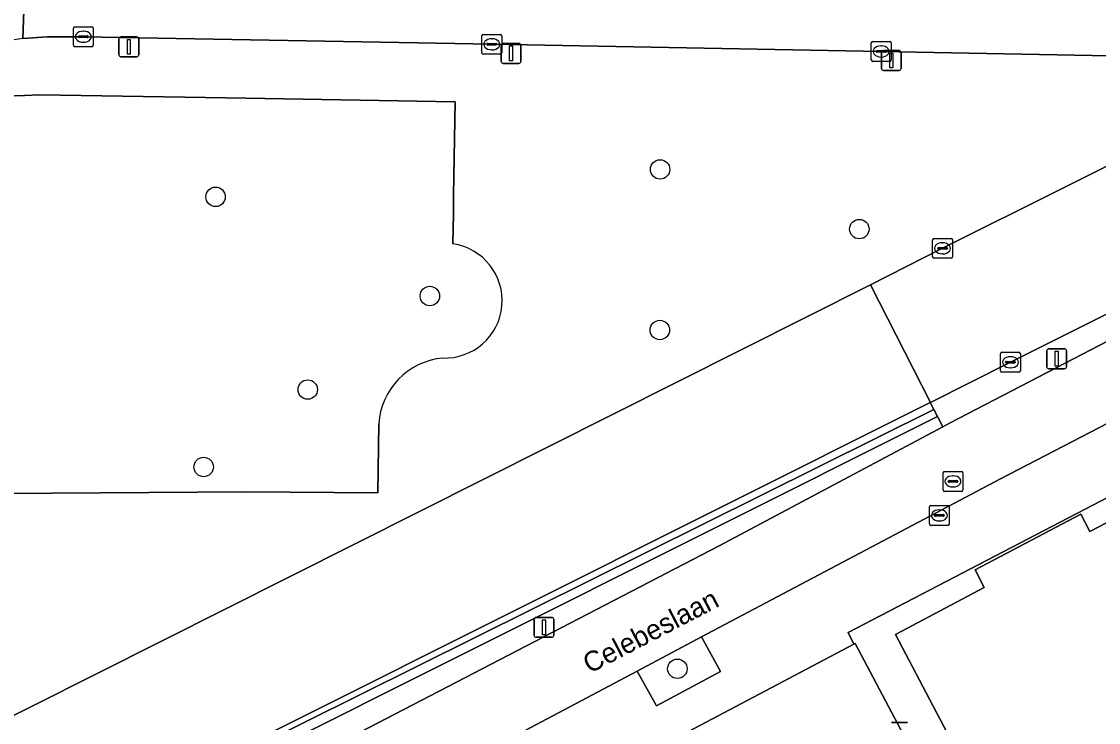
# Model space of a CAD drawing. Extents: x 162879 to 165540, y 384011 to 385181.
# Drawn here: x 162988.7 to 163042.9, y 384224.4 to 384259.7 of the extents above; entities that cross this region are included whole.
import ezdxf

# ---------------------------------------------------------------- set-up
doc = ezdxf.new("R2010")
doc.units = 0
for name, color, linetype in [('IMGEO_Berm_groen', 7, 'Continuous'), ('IMGEO_Berm_open', 7, 'Continuous'), ('IMGEO_Boom', 7, 'Continuous'), ('IMGEO_Fietspad_gesloten', 7, 'Continuous'), ('IMGEO_Groenvoorziening', 7, 'Continuous'), ('IMGEO_Kolk', 7, 'Continuous'), ('IMGEO_Lichtmast', 7, 'Continuous'), ('IMGEO_Muur', 7, 'Continuous'), ('IMGEO_Openbare_ruimte_label', 7, 'Continuous'), ('IMGEO_Parkeervlak_open', 7, 'Continuous'), ('IMGEO_Rijbaan_lokaal_gesloten', 7, 'Continuous'), ('IMGEO_Rijbaan_lokaal_open', 7, 'Continuous'), ('IMGEO_Rijbaan_regionaal_gesloten', 7, 'Continuous'), ('IMGEO_Rioolput', 7, 'Continuous'), ('IMGEO_Verkeerseiland_open', 7, 'Continuous'), ('IMGEO_Voetpad_onverhard', 7, 'Continuous'), ('IMGEO_Voetpad_open', 7, 'Continuous')]:
    doc.layers.add(name, color=color, linetype=linetype)

msp = doc.modelspace()

# ---------------------------------------------------------------- linework, layer by layer
at = {"layer": 'IMGEO_Berm_groen'}
for points in [[(163048.953, 384257.731), (163045.81, 384257.88), (163043.434, 384257.933), (163031.941, 384258.147), (163012.363, 384258.506), (162991.826, 384258.886), (162990.027, 384258.876), (162988.781, 384258.793)], [(163010.404, 384248.476), (163010.429, 384250), (163010.444, 384250.927), (163010.506, 384254.69), (163010.521, 384255.618), (163000, 384255.799), (162996.931, 384255.852), (162989.625, 384255.961), (162988.873, 384255.939), (162983.391, 384255.751)], [(162983.391, 384255.751), (162988.873, 384255.939), (162989.625, 384255.961), (162996.931, 384255.852), (163000, 384255.799), (163010.521, 384255.618), (163010.506, 384254.69), (163010.444, 384250.927), (163010.429, 384250), (163010.404, 384248.476)], [(162985.976, 384223.591), (163031.406, 384246.417), (163035.025, 384248.253), (163047.128, 384254.295)], [(162972.327, 384237.887), (162974.021, 384236.951), (162975.613, 384235.849), (163000, 384236.01), (163006.636, 384235.968), (163006.675, 384239.422)], [(163006.675, 384239.422), (163006.636, 384235.968), (163000, 384236.01), (162975.613, 384235.849)]]:
    msp.add_lwpolyline(points, dxfattribs=at)
for centre, radius, start, end in [((162995.742, 384213.765), 45.562, 98.788, 116.0822), ((163009.999, 384245.62), 2.884, 267.7669, 81.9361), ((163009.999, 384245.62), 2.884, 267.7669, 81.9361), ((163010.234, 384239.188), 3.567, 95.5899, 176.2356), ((163010.234, 384239.188), 3.567, 95.5899, 176.2356)]:
    msp.add_arc(centre, radius, start, end, dxfattribs=at)
at = {"layer": 'IMGEO_Berm_open'}
for points in [[(162947.574, 384196.509), (162949.271, 384197.384), (163000, 384222.957), (163034.579, 384240.157)], [(163034.579, 384240.157), (163034.397, 384240.497), (162949.477, 384198.002)]]:
    msp.add_lwpolyline(points, dxfattribs=at)
at = {"layer": 'IMGEO_Boom'}
for centre in [(163020.825, 384252.217), (162998.475, 384250.839), (163030.841, 384249.219), (163009.249, 384245.853), (163020.811, 384244.148), (163003.109, 384241.152), (162997.875, 384237.259), (163021.693, 384227.118)]:
    msp.add_circle(centre, 0.489, dxfattribs=at)
at = {"layer": 'IMGEO_Fietspad_gesloten'}
for points in [[(163034.397, 384240.497), (163034.42, 384240.509), (163031.406, 384246.417), (162985.976, 384223.591), (162975.103, 384218.147), (162946.359, 384203.806)], [(162949.477, 384198.002), (163034.397, 384240.497)]]:
    msp.add_lwpolyline(points, dxfattribs=at)
at = {"layer": 'IMGEO_Groenvoorziening'}
msp.add_lwpolyline([(163046.764, 384236.284), (163046.789, 384236.297), (163046.732, 384236.407), (163046.287, 384237.263), (163030.287, 384228.938), (163030.573, 384228.36), (163030.638, 384228.394), (163040.222, 384210.272), (163041.946, 384211.188), (163032.652, 384228.845), (163037.115, 384231.211), (163036.667, 384232.088), (163041.974, 384234.886), (163042.428, 384234.014)], close=True, dxfattribs=at)
at = {"layer": 'IMGEO_Kolk'}
for p, q in [((162991.325, 384258.46), (162991.325, 384259.312)), ((162991.4, 384259.386), (162992.252, 384259.386)), ((162991.813, 384259.166), (162991.838, 384259.166)), ((162992.326, 384259.312), (162992.326, 384258.46)), ((162991.584, 384258.88), (162991.584, 384258.892)), ((162992.022, 384258.843), (162991.624, 384258.843)), ((162991.627, 384258.929), (162992.025, 384258.929)), ((162991.836, 384258.606), (162991.811, 384258.606)), ((162992.068, 384258.892), (162992.068, 384258.88)), ((163011.862, 384258.08), (163011.862, 384258.932)), ((163011.937, 384259.006), (163012.789, 384259.006)), ((163012.121, 384258.5), (163012.121, 384258.512)), ((163012.164, 384258.549), (163012.562, 384258.549)), ((163012.35, 384258.786), (163012.375, 384258.786)), ((163012.605, 384258.512), (163012.605, 384258.5)), ((163012.863, 384258.932), (163012.863, 384258.08)), ((163031.44, 384257.721), (163031.44, 384258.573)), ((163031.515, 384258.647), (163032.367, 384258.647)), ((163032.441, 384258.573), (163032.441, 384257.721)), ((162992.252, 384258.386), (162991.4, 384258.386)), ((163012.789, 384258.006), (163011.937, 384258.006)), ((163012.559, 384258.463), (163012.161, 384258.463)), ((163012.373, 384258.226), (163012.348, 384258.226)), ((163031.699, 384258.141), (163031.699, 384258.153)), ((163032.137, 384258.104), (163031.739, 384258.104)), ((163031.742, 384258.19), (163032.14, 384258.19)), ((163031.928, 384258.427), (163031.953, 384258.427)), ((163032.183, 384258.153), (163032.183, 384258.141)), ((163032.367, 384257.647), (163031.515, 384257.647)), ((163031.951, 384257.867), (163031.926, 384257.867)), ((163034.524, 384247.827), (163034.524, 384248.679)), ((163034.599, 384248.753), (163035.451, 384248.753)), ((163034.783, 384248.247), (163034.783, 384248.259)), ((163034.826, 384248.296), (163035.224, 384248.296)), ((163035.012, 384248.533), (163035.037, 384248.533)), ((163035.267, 384248.259), (163035.267, 384248.247)), ((163035.525, 384248.679), (163035.525, 384247.827)), ((163035.451, 384247.753), (163034.599, 384247.753)), ((163035.221, 384248.21), (163034.823, 384248.21)), ((163035.035, 384247.973), (163035.01, 384247.973)), ((163037.939, 384242.1), (163037.939, 384242.952)), ((163038.014, 384243.026), (163038.866, 384243.026)), ((163038.427, 384242.806), (163038.452, 384242.806)), ((163038.94, 384242.952), (163038.94, 384242.1)), ((163038.198, 384242.52), (163038.198, 384242.532)), ((163038.636, 384242.483), (163038.238, 384242.483)), ((163038.241, 384242.569), (163038.639, 384242.569)), ((163038.682, 384242.532), (163038.682, 384242.52)), ((163038.866, 384242.026), (163038.014, 384242.026)), ((163038.45, 384242.246), (163038.425, 384242.246)), ((163034.365, 384234.401), (163034.365, 384235.253)), ((163034.44, 384235.327), (163035.292, 384235.327)), ((163035.366, 384235.253), (163035.366, 384234.401)), ((163034.624, 384234.821), (163034.624, 384234.833)), ((163035.062, 384234.784), (163034.664, 384234.784)), ((163034.667, 384234.87), (163035.065, 384234.87)), ((163034.853, 384235.107), (163034.878, 384235.107)), ((163035.108, 384234.833), (163035.108, 384234.821)), ((163035.292, 384234.327), (163034.44, 384234.327)), ((163034.876, 384234.547), (163034.851, 384234.547))]:
    msp.add_line(p, q, dxfattribs=at)
for points in [[(162991.325, 384258.46), (162991.325, 384259.312)], [(162991.4, 384259.386), (162992.252, 384259.386)], [(162992.326, 384259.312), (162992.326, 384258.46)], [(163011.862, 384258.08), (163011.862, 384258.932)], [(163011.937, 384259.006), (163012.789, 384259.006)], [(163012.863, 384258.932), (163012.863, 384258.08)], [(163031.44, 384257.721), (163031.44, 384258.573)], [(163031.515, 384258.647), (163032.367, 384258.647)], [(163032.441, 384258.573), (163032.441, 384257.721)], [(162992.252, 384258.386), (162991.4, 384258.386)], [(163012.789, 384258.006), (163011.937, 384258.006)], [(163032.367, 384257.647), (163031.515, 384257.647)], [(163034.524, 384247.827), (163034.524, 384248.679)], [(163034.599, 384248.753), (163035.451, 384248.753)], [(163035.525, 384248.679), (163035.525, 384247.827)], [(163035.451, 384247.753), (163034.599, 384247.753)], [(163037.939, 384242.1), (163037.939, 384242.952)], [(163038.014, 384243.026), (163038.866, 384243.026)], [(163038.94, 384242.952), (163038.94, 384242.1)], [(163038.866, 384242.026), (163038.014, 384242.026)], [(163034.365, 384234.401), (163034.365, 384235.253)], [(163034.44, 384235.327), (163035.292, 384235.327)], [(163035.366, 384235.253), (163035.366, 384234.401)], [(163035.292, 384234.327), (163034.44, 384234.327)]]:
    msp.add_lwpolyline(points, dxfattribs=at)
for centre, radius, start, end in [((162991.402, 384259.31), 0.0765, 91.552, 178.448), ((162991.402, 384259.31), 0.0765, 91.552, 178.448), ((162992.25, 384259.31), 0.0765, 1.552, 88.448), ((162992.25, 384259.31), 0.0765, 1.552, 88.448), ((162991.624, 384258.889), 0.0403, 85.8775, 175.7526), ((162991.621, 384258.879), 0.0366, 178.938, 274.7102), ((162992.025, 384258.886), 0.043, 264.8664, 352.4533), ((162992.029, 384258.891), 0.0386, 1.7309, 96.639), ((163011.939, 384258.93), 0.0765, 91.552, 178.448), ((163011.939, 384258.93), 0.0765, 91.552, 178.448), ((163012.161, 384258.509), 0.0403, 85.8775, 175.7526), ((163012.566, 384258.511), 0.0386, 1.7309, 96.639), ((163012.787, 384258.93), 0.0765, 1.552, 88.448), ((163012.787, 384258.93), 0.0765, 1.552, 88.448), ((163031.517, 384258.571), 0.0765, 91.552, 178.448), ((163031.517, 384258.571), 0.0765, 91.552, 178.448), ((163032.365, 384258.571), 0.0765, 1.552, 88.448), ((163032.365, 384258.571), 0.0765, 1.552, 88.448), ((162991.402, 384258.462), 0.0765, 181.552, 268.448), ((162991.402, 384258.462), 0.0765, 181.552, 268.448), ((162992.25, 384258.462), 0.0765, 271.552, 358.448), ((162992.25, 384258.462), 0.0765, 271.552, 358.448), ((163011.939, 384258.082), 0.0765, 181.552, 268.448), ((163011.939, 384258.082), 0.0765, 181.552, 268.448), ((163012.158, 384258.499), 0.0366, 178.938, 274.7102), ((163012.562, 384258.506), 0.043, 264.8664, 352.4533), ((163012.787, 384258.082), 0.0765, 271.552, 358.448), ((163012.787, 384258.082), 0.0765, 271.552, 358.448), ((163031.739, 384258.15), 0.0403, 85.8775, 175.7526), ((163031.736, 384258.14), 0.0366, 178.938, 274.7102), ((163032.14, 384258.147), 0.043, 264.8664, 352.4533), ((163032.144, 384258.152), 0.0386, 1.7309, 96.639), ((163031.517, 384257.723), 0.0765, 181.552, 268.448), ((163031.517, 384257.723), 0.0765, 181.552, 268.448), ((163032.365, 384257.723), 0.0765, 271.552, 358.448), ((163032.365, 384257.723), 0.0765, 271.552, 358.448), ((163034.601, 384248.677), 0.0765, 91.552, 178.448), ((163034.601, 384248.677), 0.0765, 91.552, 178.448), ((163034.823, 384248.256), 0.0403, 85.8775, 175.7526), ((163034.82, 384248.246), 0.0366, 178.938, 274.7102), ((163035.224, 384248.253), 0.043, 264.8664, 352.4533), ((163035.228, 384248.258), 0.0386, 1.7309, 96.639), ((163035.449, 384248.677), 0.0765, 1.552, 88.448), ((163035.449, 384248.677), 0.0765, 1.552, 88.448), ((163034.601, 384247.829), 0.0765, 181.552, 268.448), ((163034.601, 384247.829), 0.0765, 181.552, 268.448), ((163035.449, 384247.829), 0.0765, 271.552, 358.448), ((163035.449, 384247.829), 0.0765, 271.552, 358.448), ((163038.016, 384242.95), 0.0765, 91.552, 178.448), ((163038.016, 384242.95), 0.0765, 91.552, 178.448), ((163038.864, 384242.95), 0.0765, 1.552, 88.448), ((163038.864, 384242.95), 0.0765, 1.552, 88.448), ((163038.238, 384242.529), 0.0403, 85.8775, 175.7526), ((163038.235, 384242.519), 0.0366, 178.938, 274.7102), ((163038.639, 384242.526), 0.043, 264.8664, 352.4533), ((163038.643, 384242.531), 0.0386, 1.7309, 96.639), ((163038.016, 384242.102), 0.0765, 181.552, 268.448), ((163038.016, 384242.102), 0.0765, 181.552, 268.448), ((163038.864, 384242.102), 0.0765, 271.552, 358.448), ((163038.864, 384242.102), 0.0765, 271.552, 358.448), ((163034.442, 384235.251), 0.0765, 91.552, 178.448), ((163034.442, 384235.251), 0.0765, 91.552, 178.448), ((163035.29, 384235.251), 0.0765, 1.552, 88.448), ((163035.29, 384235.251), 0.0765, 1.552, 88.448), ((163034.664, 384234.83), 0.0403, 85.8775, 175.7526), ((163034.661, 384234.82), 0.0366, 178.938, 274.7102), ((163035.065, 384234.827), 0.043, 264.8664, 352.4533), ((163035.069, 384234.832), 0.0386, 1.7309, 96.639), ((163034.442, 384234.403), 0.0765, 181.552, 268.448), ((163034.442, 384234.403), 0.0765, 181.552, 268.448), ((163035.29, 384234.403), 0.0765, 271.552, 358.448), ((163035.29, 384234.403), 0.0765, 271.552, 358.448)]:
    msp.add_arc(centre, radius, start, end, dxfattribs=at)
for centre, major_axis, ratio, start_param, end_param in [((162991.812, 384258.886), (-0.387, 0.002), 0.722429, 4.712389, 7.853982), ((162991.837, 384258.886), (-0.39, 0.002), 0.717154, 1.570796, 4.712389), ((163012.349, 384258.506), (-0.387, 0.002), 0.722429, 4.712389, 7.853982), ((163012.374, 384258.506), (-0.39, 0.002), 0.717154, 1.570796, 4.712389), ((163031.927, 384258.147), (-0.387, 0.002), 0.722429, 4.712389, 7.853982), ((163031.952, 384258.147), (-0.39, 0.002), 0.717154, 1.570796, 4.712389), ((163035.011, 384248.253), (-0.387, 0.002), 0.722429, 4.712389, 7.853982), ((163035.036, 384248.253), (-0.39, 0.002), 0.717154, 1.570796, 4.712389), ((163038.426, 384242.526), (-0.387, 0.002), 0.722429, 4.712389, 7.853982), ((163038.451, 384242.526), (-0.39, 0.002), 0.717154, 1.570796, 4.712389), ((163034.852, 384234.827), (-0.387, 0.002), 0.722429, 4.712389, 7.853982), ((163034.877, 384234.827), (-0.39, 0.002), 0.717154, 1.570796, 4.712389)]:
    msp.add_ellipse(centre, major_axis=major_axis, ratio=ratio, start_param=start_param, end_param=end_param, dxfattribs=at)
at = {"layer": 'IMGEO_Lichtmast'}
for p, q in [((162993.618, 384257.979), (162993.618, 384258.779)), ((162993.618, 384258.779), (162993.618, 384257.979)), ((162993.718, 384258.879), (162994.508, 384258.879)), ((162994.508, 384258.879), (162993.718, 384258.879)), ((162994.608, 384258.779), (162994.608, 384257.979)), ((162994.608, 384257.979), (162994.608, 384258.779)), ((163012.936, 384258.549), (163013.726, 384258.549)), ((163013.726, 384258.549), (163012.936, 384258.549)), ((163012.836, 384257.649), (163012.836, 384258.449)), ((163012.836, 384258.449), (163012.836, 384257.649)), ((163013.826, 384258.449), (163013.826, 384257.649)), ((163013.826, 384257.649), (163013.826, 384258.449)), ((163031.953, 384257.292), (163031.953, 384258.092)), ((163031.953, 384258.092), (163031.953, 384257.292)), ((163032.053, 384258.192), (163032.843, 384258.192)), ((163032.843, 384258.192), (163032.053, 384258.192)), ((163032.943, 384258.092), (163032.943, 384257.292)), ((163032.943, 384257.292), (163032.943, 384258.092)), ((162994.508, 384257.879), (162993.718, 384257.879)), ((162993.718, 384257.879), (162994.508, 384257.879)), ((163013.726, 384257.549), (163012.936, 384257.549)), ((163012.936, 384257.549), (163013.726, 384257.549)), ((163032.843, 384257.192), (163032.053, 384257.192)), ((163032.053, 384257.192), (163032.843, 384257.192)), ((163040.268, 384242.3), (163040.268, 384243.1)), ((163040.268, 384243.1), (163040.268, 384242.3)), ((163040.368, 384243.2), (163041.158, 384243.2)), ((163041.158, 384243.2), (163040.368, 384243.2)), ((163041.258, 384243.1), (163041.258, 384242.3)), ((163041.258, 384242.3), (163041.258, 384243.1)), ((163041.158, 384242.2), (163040.368, 384242.2)), ((163040.368, 384242.2), (163041.158, 384242.2)), ((163014.489, 384228.803), (163014.489, 384229.603)), ((163014.489, 384229.603), (163014.489, 384228.803)), ((163014.589, 384229.703), (163015.379, 384229.703)), ((163015.379, 384229.703), (163014.589, 384229.703)), ((163015.479, 384229.603), (163015.479, 384228.803)), ((163015.479, 384228.803), (163015.479, 384229.603)), ((163015.379, 384228.703), (163014.589, 384228.703)), ((163014.589, 384228.703), (163015.379, 384228.703)), ((163032.466, 384224.421), (163033.256, 384224.421)), ((163033.256, 384224.421), (163032.466, 384224.421))]:
    msp.add_line(p, q, dxfattribs=at)
for points in [[(162994.038, 384258.754), (162994.188, 384258.754), (162994.188, 384258.004), (162994.038, 384258.004), (162994.038, 384258.754)], [(163013.256, 384258.424), (163013.406, 384258.424), (163013.406, 384257.674), (163013.256, 384257.674), (163013.256, 384258.424)], [(163032.373, 384258.067), (163032.523, 384258.067), (163032.523, 384257.317), (163032.373, 384257.317), (163032.373, 384258.067)], [(163040.688, 384243.075), (163040.838, 384243.075), (163040.838, 384242.325), (163040.688, 384242.325), (163040.688, 384243.075)], [(163014.909, 384229.578), (163015.059, 384229.578), (163015.059, 384228.828), (163014.909, 384228.828), (163014.909, 384229.578)]]:
    msp.add_lwpolyline(points, dxfattribs=at)
for centre, start, end in [((162993.718, 384258.779), 90, 180), ((162993.718, 384258.779), 90, 180), ((162994.508, 384258.779), 0, 90), ((162994.508, 384258.779), 360, 90), ((163012.936, 384258.449), 90, 180), ((163012.936, 384258.449), 90, 180), ((163013.726, 384258.449), 0, 90), ((163013.726, 384258.449), 360, 90), ((162993.718, 384257.979), 180, 270), ((162993.718, 384257.979), 180, 270), ((162994.508, 384257.979), 270, 0), ((162994.508, 384257.979), 270, 0), ((163032.053, 384258.092), 90, 180), ((163032.053, 384258.092), 90, 180), ((163032.843, 384258.092), 0, 90), ((163032.843, 384258.092), 360, 90), ((163012.936, 384257.649), 180, 270), ((163012.936, 384257.649), 180, 270), ((163013.726, 384257.649), 270, 0), ((163013.726, 384257.649), 270, 0), ((163032.053, 384257.292), 180, 270), ((163032.053, 384257.292), 180, 270), ((163032.843, 384257.292), 270, 0), ((163032.843, 384257.292), 270, 0), ((163040.368, 384243.1), 90, 180), ((163040.368, 384243.1), 90, 180), ((163041.158, 384243.1), 0, 90), ((163041.158, 384243.1), 360, 90), ((163040.368, 384242.3), 180, 270), ((163040.368, 384242.3), 180, 270), ((163041.158, 384242.3), 270, 0), ((163041.158, 384242.3), 270, 0), ((163014.589, 384229.603), 90, 180), ((163014.589, 384229.603), 90, 180), ((163015.379, 384229.603), 0, 90), ((163015.379, 384229.603), 360, 90), ((163014.589, 384228.803), 180, 270), ((163014.589, 384228.803), 180, 270), ((163015.379, 384228.803), 270, 0), ((163015.379, 384228.803), 270, 0)]:
    msp.add_arc(centre, 0.1, start, end, dxfattribs=at)
at = {"layer": 'IMGEO_Muur'}
for points in [[(163034.767, 384239.806), (163034.579, 384240.157), (163000, 384222.957), (162949.271, 384197.384), (162947.574, 384196.509)], [(162947.981, 384196.226), (162949.51, 384197.083), (163000, 384222.384), (163034.767, 384239.806)]]:
    msp.add_lwpolyline(points, dxfattribs=at)
at = {"layer": 'IMGEO_Parkeervlak_open'}
msp.add_lwpolyline([(163057.039, 384216.873), (163047.577, 384234.747), (163046.764, 384236.284), (163042.428, 384234.014), (163041.974, 384234.886), (163036.667, 384232.088), (163037.115, 384231.211), (163032.652, 384228.845), (163041.946, 384211.188), (163040.222, 384210.272), (163041.173, 384208.482)], close=True, dxfattribs=at)
at = {"layer": 'IMGEO_Rijbaan_lokaal_gesloten'}
msp.add_lwpolyline([(163069.325, 384258.023), (163070.11, 384258.418), (163071.935, 384259.339), (163069.992, 384263.975), (163060.533, 384260.029), (163050.998, 384256.102), (163049.129, 384255.319), (163048.235, 384254.869), (163047.128, 384254.295), (163035.025, 384248.253), (163031.406, 384246.417), (163034.42, 384240.509), (163038.44, 384242.526), (163056.687, 384251.652)], close=True, dxfattribs=at)
at = {"layer": 'IMGEO_Rijbaan_lokaal_open'}
msp.add_lwpolyline([(163045.835, 384261.901), (163044.189, 384261.925), (163033.666, 384262.096), (163023.085, 384262.29), (163015.053, 384262.437), (163012.114, 384262.491), (162988.941, 384263.017), (162988.781, 384258.793), (162990.027, 384258.876), (162991.826, 384258.886), (163012.363, 384258.506), (163031.941, 384258.147), (163043.434, 384257.933), (163045.81, 384257.88)], close=True, dxfattribs=at)
for points in [[(163057.072, 384250.727), (163035.414, 384239.48), (163035.046, 384239.284), (163023.796, 384233.299), (163000, 384220.956), (162955.281, 384197.725), (162949.67, 384195.053)], [(163006.586, 384220.12), (163010.26, 384222.03), (163010.902, 384222.364), (163019.672, 384227.003), (163022.913, 384228.717), (163037.941, 384236.666), (163054.656, 384245.325), (163059.442, 384247.777)], [(163044.864, 384201.274), (163041.173, 384208.482), (163040.222, 384210.272), (163030.638, 384228.394), (163030.573, 384228.36), (163014.549, 384219.892), (163014.301, 384219.761), (163017.293, 384214.082), (163018.429, 384212.041), (163018.152, 384211.894), (163024.825, 384199.304), (163025.066, 384199.433), (163026.131, 384197.372), (163028.279, 384193.317), (163012.433, 384184.826), (163020.858, 384168.961), (163032.586, 384175.227), (163036.694, 384177.404), (163038.642, 384173.779), (163039.758, 384171.616), (163032.709, 384167.878)]]:
    msp.add_lwpolyline(points, dxfattribs=at)
at = {"layer": 'IMGEO_Rijbaan_regionaal_gesloten'}
msp.add_lwpolyline([(162988.781, 384258.793), (162988.941, 384263.017)], dxfattribs=at)
msp.add_arc((162995.742, 384213.765), 45.562, 98.788, 116.0822, dxfattribs=at)
at = {"layer": 'IMGEO_Rioolput'}
for p, q in [((163035.048, 384236.11), (163035.048, 384236.962)), ((163035.123, 384237.036), (163035.975, 384237.036)), ((163036.049, 384236.962), (163036.049, 384236.11)), ((163035.307, 384236.53), (163035.307, 384236.542)), ((163035.745, 384236.493), (163035.347, 384236.493)), ((163035.35, 384236.579), (163035.748, 384236.579)), ((163035.536, 384236.816), (163035.561, 384236.816)), ((163035.791, 384236.542), (163035.791, 384236.53)), ((163035.975, 384236.036), (163035.123, 384236.036)), ((163035.559, 384236.256), (163035.534, 384236.256))]:
    msp.add_line(p, q, dxfattribs=at)
for points in [[(163035.048, 384236.11), (163035.048, 384236.962)], [(163035.123, 384237.036), (163035.975, 384237.036)], [(163036.049, 384236.962), (163036.049, 384236.11)], [(163035.975, 384236.036), (163035.123, 384236.036)]]:
    msp.add_lwpolyline(points, dxfattribs=at)
for centre, radius, start, end in [((163035.125, 384236.96), 0.0765, 91.552, 178.448), ((163035.125, 384236.96), 0.0765, 91.552, 178.448), ((163035.973, 384236.96), 0.0765, 1.552, 88.448), ((163035.973, 384236.96), 0.0765, 1.552, 88.448), ((163035.347, 384236.539), 0.0403, 85.8775, 175.7526), ((163035.344, 384236.529), 0.0366, 178.938, 274.7102), ((163035.748, 384236.536), 0.043, 264.8664, 352.4533), ((163035.752, 384236.541), 0.0386, 1.7309, 96.639), ((163035.125, 384236.112), 0.0765, 181.552, 268.448), ((163035.125, 384236.112), 0.0765, 181.552, 268.448), ((163035.973, 384236.112), 0.0765, 271.552, 358.448), ((163035.973, 384236.112), 0.0765, 271.552, 358.448)]:
    msp.add_arc(centre, radius, start, end, dxfattribs=at)
for centre, major_axis, ratio, start_param, end_param in [((163035.535, 384236.536), (-0.387, 0.002), 0.722429, 4.712389, 7.853982), ((163035.56, 384236.536), (-0.39, 0.002), 0.717154, 1.570796, 4.712389)]:
    msp.add_ellipse(centre, major_axis=major_axis, ratio=ratio, start_param=start_param, end_param=end_param, dxfattribs=at)
at = {"layer": 'IMGEO_Verkeerseiland_open'}
msp.add_lwpolyline([(163056.687, 384251.652), (163038.44, 384242.526), (163034.42, 384240.509), (163034.397, 384240.497), (163034.579, 384240.157), (163034.767, 384239.806), (163035.046, 384239.284), (163035.414, 384239.48), (163057.072, 384250.727)], dxfattribs=at)
at = {"layer": 'IMGEO_Voetpad_onverhard'}
msp.add_lwpolyline([(163022.913, 384228.717), (163019.672, 384227.003), (163020.635, 384225.255), (163023.854, 384226.982)], close=True, dxfattribs=at)
at = {"layer": 'IMGEO_Voetpad_open'}
for points in [[(163014.307, 384220.37), (163014.549, 384219.892), (163030.573, 384228.36), (163030.287, 384228.938), (163046.287, 384237.263), (163046.732, 384236.407), (163046.789, 384236.297), (163046.764, 384236.284), (163047.577, 384234.747), (163051.264, 384236.696), (163049.969, 384239.189), (163062.352, 384245.606), (163064.184, 384245.26), (163063.465, 384246.618)], [(163054.656, 384245.325), (163037.941, 384236.666), (163022.913, 384228.717), (163023.854, 384226.982), (163020.635, 384225.255), (163019.672, 384227.003), (163010.902, 384222.364), (163010.26, 384222.03), (163011.308, 384220.177), (163007.583, 384218.251), (163006.586, 384220.12), (163000, 384216.696), (162961.586, 384196.6)], [(162949.67, 384195.053), (162955.281, 384197.725), (163000, 384220.956), (163023.796, 384233.299), (163035.046, 384239.284), (163034.767, 384239.806), (163000, 384222.384), (162949.51, 384197.083), (162947.981, 384196.226)]]:
    msp.add_lwpolyline(points, dxfattribs=at)

# ---------------------------------------------------------------- texts
at = {"layer": 'IMGEO_Openbare_ruimte_label'}
msp.add_text('Celebeslaan', height=1, rotation=27.5131, dxfattribs=at).set_placement((163017.279, 384226.857))

doc.saveas('drawing.dxf')
